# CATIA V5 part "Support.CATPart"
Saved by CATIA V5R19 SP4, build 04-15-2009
Part number: Support
Bounding box of the stored display mesh (mm): x 0 to 120, y 0 to 250, z -860 to 0
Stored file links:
  G:\EU_thinkMotion\CFAO_2010\MMS_groupe1\MMS_groupe1\OK\ptangsittisin\TANGSITTISIN\TANGSITTISIN\Support.CATPart
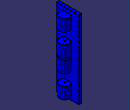
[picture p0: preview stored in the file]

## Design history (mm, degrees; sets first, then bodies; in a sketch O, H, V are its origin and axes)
Parameters
  `Support Width` = 250 mm
Body1 (main body)
  Sketch1 on yz-plane, origin (0, 0, 0), H (0, 1, 0), V (0, 0, 1)
    line L1 (0, 0) -> (250, 0)
    line L2 (250, 0) -> (250, -860)
    line L3 (250, -860) -> (0, -860)
    line L4 (0, -860) -> (0, 0)
    angle L4 L3 = 90
    angle L2 L3 = 90
    length L2 = 860 {= `Support Width` *3.44}
    length L1 = 250 {= `Support Width`}
  Pad1 "Support": profile Sketch1, direction (1, 0, 0), length 30
  Sketch2 on xy-plane, origin (0, 0, 0), H (1, 0, 0), V (0, 1, 0)
  Sketch3 on face of Pad1 from Sketch1.L1, origin (0, 0, 0), H (1, 0, 0), V (0, 1, 0)
    reference projected line E1 (30, 250) -> (30, 0) from edge [face of Pad1 from Sketch1.L1 | end face of Pad1]
    construction line L1 (30, 125) -> (100, 125)
    circle A1 centre (65, 125) radius 55
    point P5 (65, 125)
    radius A1 = 55
    distance E1 P5 = 35
  Pad2: profile Sketch3, direction (0, 0, -1), length 860
  Sketch4 on zx-plane, origin (0, 0, 0), H (-1, 0, 0), V (0, 0, 1)
    line L1 (-30, -40) -> (-120, -40)
    line L2 (-120, -40) -> (-120, 0)
    line L3 (-120, 0) -> (-30, 0)
    line L4 (-30, 0) -> (-30, -40)
    line L5 (-30, -290) -> (-120, -290)
    line L6 (-120, -290) -> (-120, -170)
    line L7 (-120, -170) -> (-30, -170)
    line L8 (-30, -170) -> (-30, -290)
    line L9 (-30, -440) -> (-120, -440)
    line L10 (-120, -440) -> (-120, -420)
    line L11 (-120, -420) -> (-30, -420)
    line L12 (-30, -420) -> (-30, -440)
    line L13 (-30, -690) -> (-120, -690)
    line L14 (-120, -690) -> (-120, -570)
    line L15 (-120, -570) -> (-30, -570)
    line L16 (-30, -570) -> (-30, -690)
    line L17 (-30, -860) -> (-120, -860)
    line L18 (-120, -860) -> (-120, -820)
    line L19 (-120, -820) -> (-30, -820)
    line L20 (-30, -820) -> (-30, -860)
  Pocket1: profile Sketch4, direction (0, 1, 0), length 250
  Sketch5 on face of Pocket1 from Sketch4.L7, origin (0, 0, -170), H (1, 0, 0), V (0, -1, 0)
    circle A1 centre (65, -125) radius 10
    radius A1 = 10
  Pocket2: profile Sketch5, direction (0, 0, 1), length 30
  Sketch6 on face of Pocket1 from Sketch4.L5, origin (0, 0, -290), H (1, 0, 0), V (0, 1, 0)
    circle A1 centre (65, 125) radius 10
    radius A1 = 10
  Pocket3: profile Sketch6, direction (0, 0, -1), length 30
  Sketch7 on face of Pocket1 from Sketch4.L15, origin (0, 0, -570), H (1, 0, 0), V (0, -1, 0)
    circle A1 centre (65, -125) radius 10
    radius A1 = 10
  Pocket4: profile Sketch7, direction (0, 0, 1), length 30
  Sketch8 on face of Pocket1 from Sketch4.L13, origin (0, 0, -690), H (1, 0, 0), V (0, 1, 0)
    circle A1 centre (65, 125) radius 10
    radius A1 = 10
  Pocket5: profile Sketch8, direction (0, 0, -1), length 30
Relations
  `Support Width` = 250 (deactivated)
